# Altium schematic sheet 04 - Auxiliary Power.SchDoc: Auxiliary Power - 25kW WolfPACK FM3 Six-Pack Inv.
size 431 x 279 mm; Date: 01/2024; DocumentNumber: CRD25DA12N-FMC; Revision: 1.2; SheetNumber: 4; SheetTotal: 8; SheetSize: B
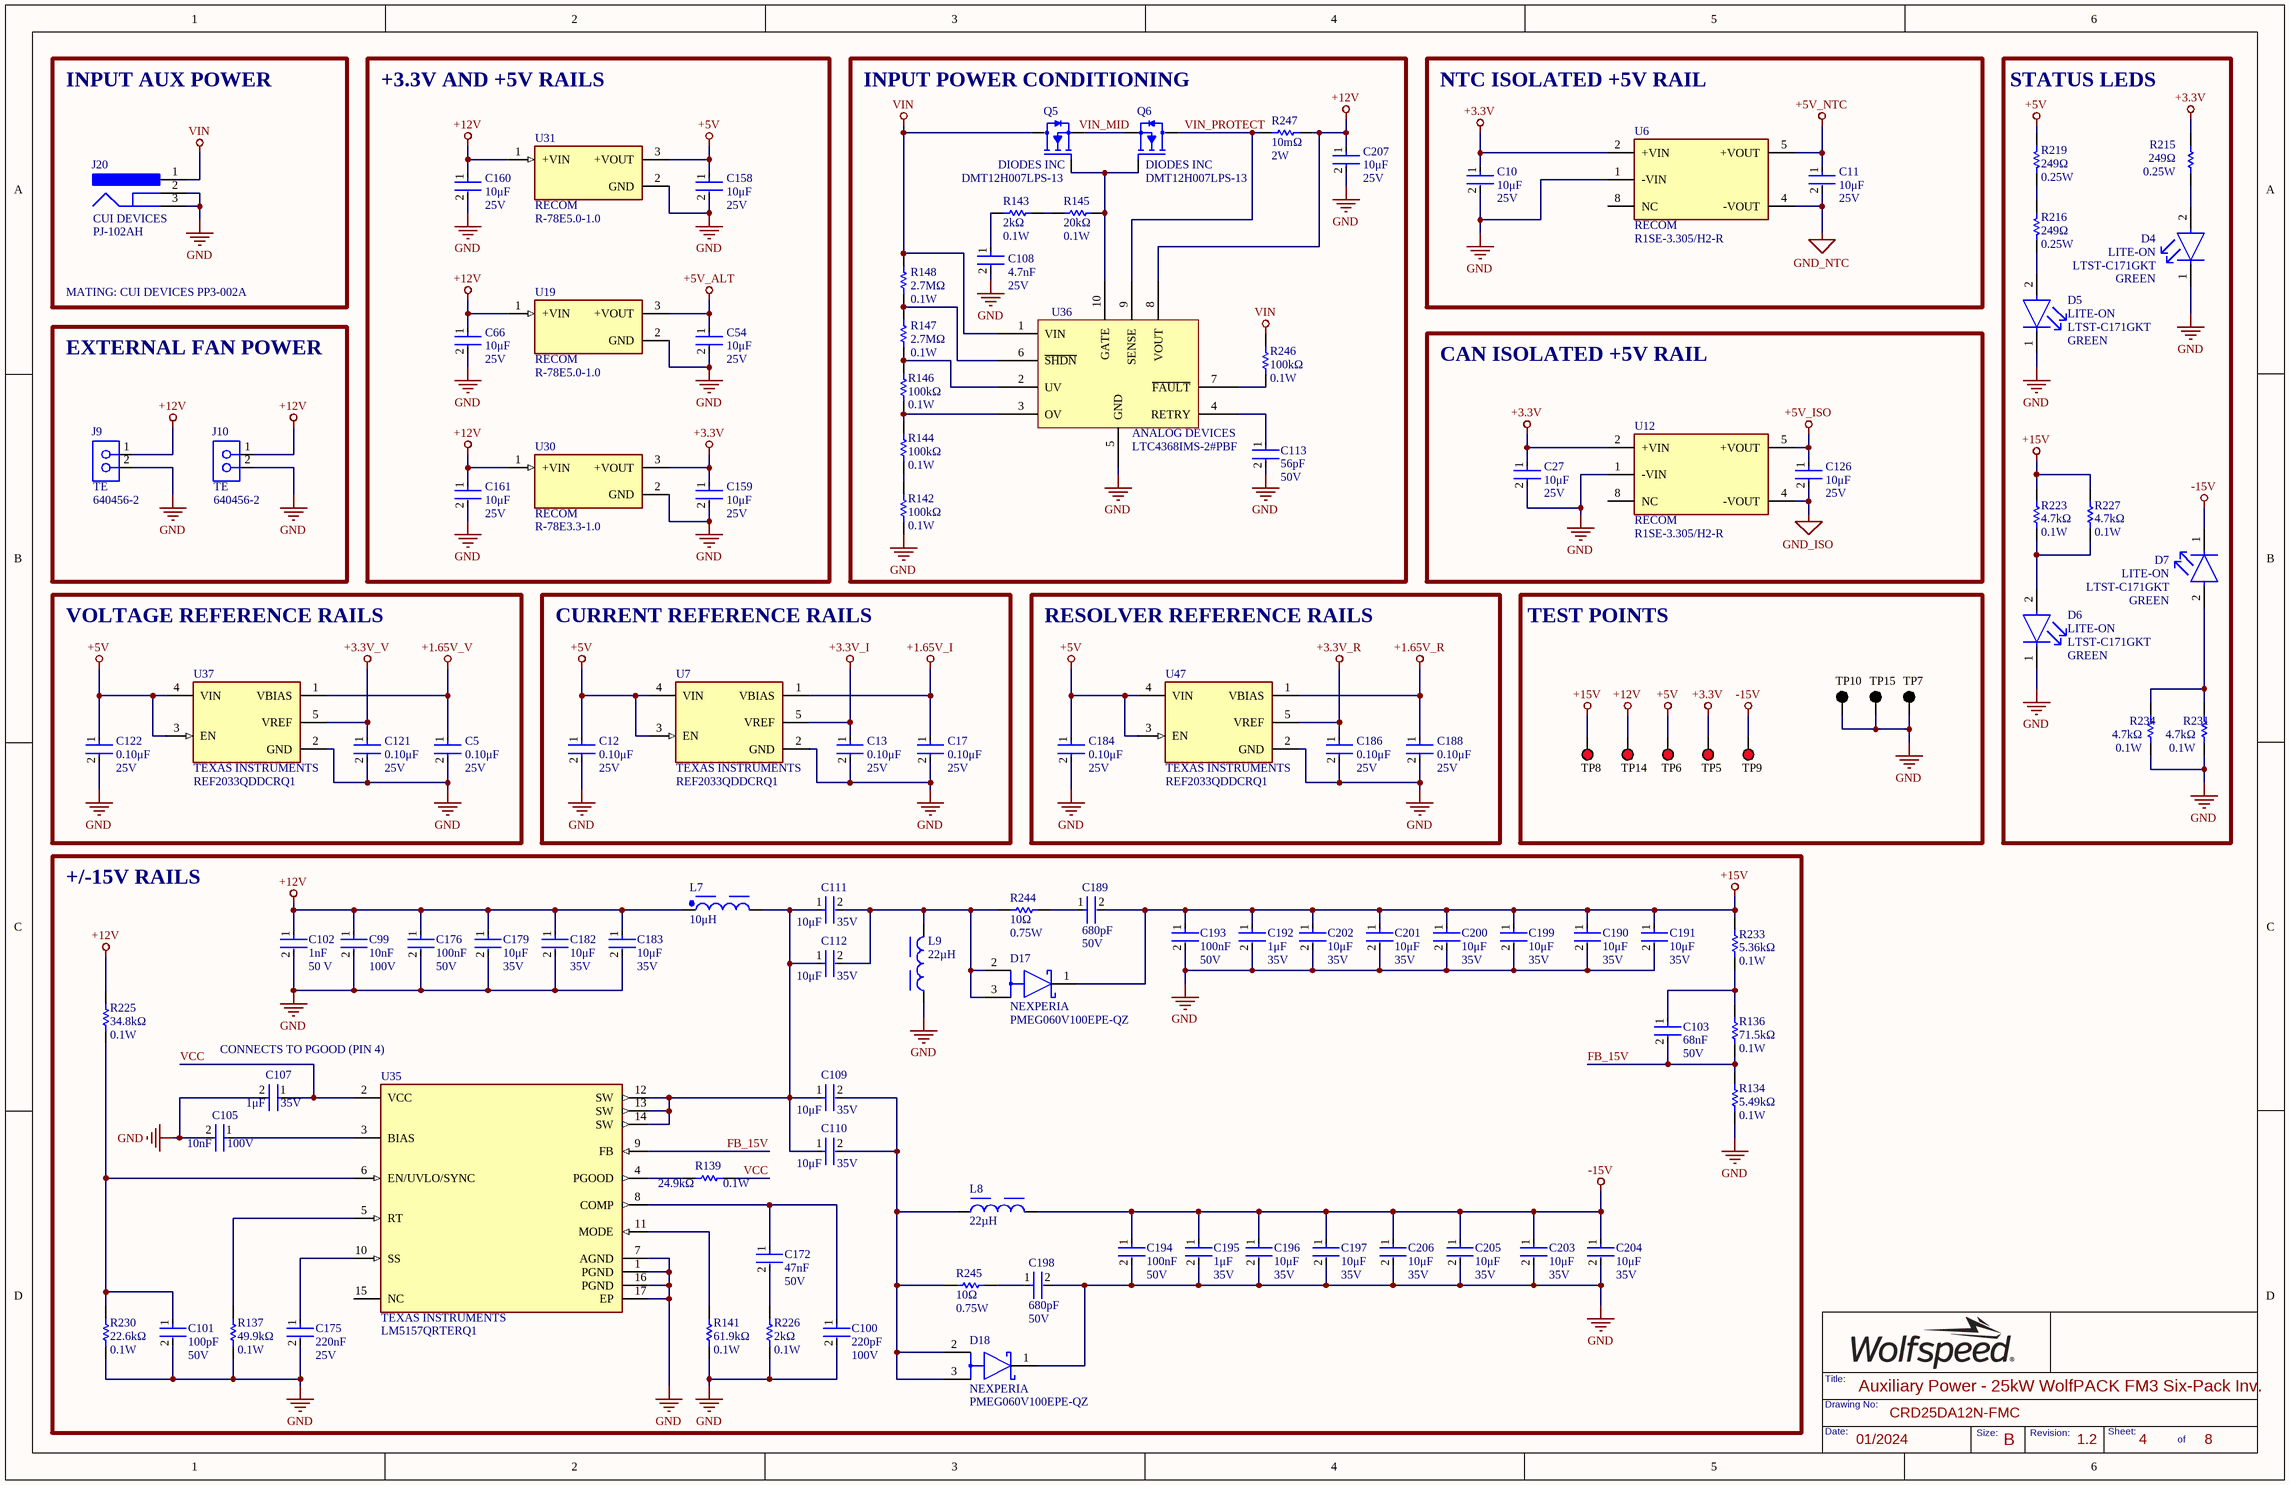
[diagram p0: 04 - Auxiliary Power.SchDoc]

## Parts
C5  Voltage Rating: 25V  Capacitance: 0.10μF  [FP-C0603C-CF-IPC_B]  (hidden comment: C0603C104K3RACTU)
C10  Voltage Rating: 25V  Capacitance: 10μF  [FP-CL31-IPC_B]  (hidden comment: CL31B106KAHSFNE)
C11  Voltage Rating: 25V  Capacitance: 10μF  [FP-CL31-IPC_B]  (hidden comment: CL31B106KAHSFNE)
C12  Voltage Rating: 25V  Capacitance: 0.10μF  [FP-C0603C-CF-IPC_B]  (hidden comment: C0603C104K3RACTU)
C13  Voltage Rating: 25V  Capacitance: 0.10μF  [FP-C0603C-CF-IPC_B]  (hidden comment: C0603C104K3RACTU)
C17  Voltage Rating: 25V  Capacitance: 0.10μF  [FP-C0603C-CF-IPC_B]  (hidden comment: C0603C104K3RACTU)
C27  Voltage Rating: 25V  Capacitance: 10μF  [FP-CL31-IPC_B]  (hidden comment: CL31B106KAHSFNE)
C54  Voltage Rating: 25V  Capacitance: 10μF  [FP-CL31-IPC_B]  (hidden comment: CL31B106KAHSFNE)
C66  Voltage Rating: 25V  Capacitance: 10μF  [FP-CL31-IPC_B]  (hidden comment: CL31B106KAHSFNE)
C99  value 10nF  Voltage Rating: 100V  [FP-C0603C-CF-IPC_B]  (hidden comment: GCM188R72A103KA37D)
C100  value 220pF  Voltage Rating: 100V  [FP-C0603C-CF-IPC_B]  (hidden comment: GCM1885C2A221JA16D)
C101  Capacitance: 100pF  Voltage: 50V  [FP-C0603C-CF-IPC_B]  (hidden comment: CL10C101JB8NNNC)
C102  Capacitance: 1nF  Voltage Rating: 50 V  [FP-C0603C-CF-IPC_B]  (hidden comment: C0603C102K5RACAUTO)
C103  value 68nF  Voltage Rating (DC): 50V  [FP-C0603C-CF-IPC_B]  (hidden comment: CGA3E2X7R1H683K080AA)
C105  value 10nF  Voltage Rating: 100V  [FP-C0603C-CF-IPC_B]  (hidden comment: GCM188R72A103KA37D)
C107  value 1μF  Voltage Rating: 35V  [FP-C0603C-CF-IPC_B]  (hidden comment: CGA3E1X7R1V105K080AC)
C108  Voltage Rating: 25V  Capacitance: 4.7nF  [FP-C0603C-CF-IPC_B]  (hidden comment: C0603C472K3RAC7867)
C109  value 10μF  Voltage Rating: 35V  [FP-C0603C-CF-IPC_B]  (hidden comment: GRM188R6YA106MA73D)
C110  value 10μF  Voltage Rating: 35V  [FP-C0603C-CF-IPC_B]  (hidden comment: GRM188R6YA106MA73D)
C111  value 10μF  Voltage Rating: 35V  [FP-C0603C-CF-IPC_B]  (hidden comment: GRM188R6YA106MA73D)
C112  value 10μF  Voltage Rating: 35V  [FP-C0603C-CF-IPC_B]  (hidden comment: GRM188R6YA106MA73D)
C113  Capacitance: 56pF  Voltage Rating: 50V  [FP-C0603C-CF-IPC_B]  (hidden comment: CL10C560JB8NNNC)
C121  Voltage Rating: 25V  Capacitance: 0.10μF  [FP-C0603C-CF-IPC_B]  (hidden comment: C0603C104K3RACTU)
C122  Voltage Rating: 25V  Capacitance: 0.10μF  [FP-C0603C-CF-IPC_B]  (hidden comment: C0603C104K3RACTU)
C126  Voltage Rating: 25V  Capacitance: 10μF  [FP-CL31-IPC_B]  (hidden comment: CL31B106KAHSFNE)
C158  Voltage Rating: 25V  Capacitance: 10μF  [FP-CL31-IPC_B]  (hidden comment: CL31B106KAHSFNE)
C159  Voltage Rating: 25V  Capacitance: 10μF  [FP-CL31-IPC_B]  (hidden comment: CL31B106KAHSFNE)
C160  Voltage Rating: 25V  Capacitance: 10μF  [FP-CL31-IPC_B]  (hidden comment: CL31B106KAHSFNE)
C161  Voltage Rating: 25V  Capacitance: 10μF  [FP-CL31-IPC_B]  (hidden comment: CL31B106KAHSFNE)
C172  value 47nF  Voltage Rating: 50V  [FP-C0603C-CF-IPC_B]  (hidden comment: CGA3E2X7R1H473K080AA)
C175  Capacitance: 220nF  Voltage: 25V  [FP-C0603C-CF-IPC_B]  (hidden comment: GCM188R71E224KA55D)
C176  value 100nF  Voltage: 50V  [FP-C0603C-CF-IPC_B]  (hidden comment: CGA3E2X7R1H104K080AA)
C179  value 10μF  Voltage Rating: 35V  [FP-C0603C-CF-IPC_B]  (hidden comment: GRM188R6YA106MA73D)
C182  value 10μF  Voltage Rating: 35V  [FP-C0603C-CF-IPC_B]  (hidden comment: GRM188R6YA106MA73D)
C183  value 10μF  Voltage Rating: 35V  [FP-C0603C-CF-IPC_B]  (hidden comment: GRM188R6YA106MA73D)
C184  Voltage Rating: 25V  Capacitance: 0.10μF  [FP-C0603C-CF-IPC_B]  (hidden comment: C0603C104K3RACTU)
C186  Voltage Rating: 25V  Capacitance: 0.10μF  [FP-C0603C-CF-IPC_B]  (hidden comment: C0603C104K3RACTU)
C188  Voltage Rating: 25V  Capacitance: 0.10μF  [FP-C0603C-CF-IPC_B]  (hidden comment: C0603C104K3RACTU)
C189  value 680pF  Voltage: 50V  [FP-C0603C-CF-IPC_B]  (hidden comment: C0603C681J5GACTU)
C190  value 10μF  Voltage Rating: 35V  [FP-C0603C-CF-IPC_B]  (hidden comment: GRM188R6YA106MA73D)
C191  value 10μF  Voltage Rating: 35V  [FP-C0603C-CF-IPC_B]  (hidden comment: GRM188R6YA106MA73D)
C192  value 1μF  Voltage Rating: 35V  [FP-C0603C-CF-IPC_B]  (hidden comment: CGA3E1X7R1V105K080AC)
C193  value 100nF  Voltage: 50V  [FP-C0603C-CF-IPC_B]  (hidden comment: CGA3E2X7R1H104K080AA)
C194  value 100nF  Voltage: 50V  [FP-C0603C-CF-IPC_B]  (hidden comment: CGA3E2X7R1H104K080AA)
C195  value 1μF  Voltage Rating: 35V  [FP-C0603C-CF-IPC_B]  (hidden comment: CGA3E1X7R1V105K080AC)
C196  value 10μF  Voltage Rating: 35V  [FP-C0603C-CF-IPC_B]  (hidden comment: GRM188R6YA106MA73D)
C197  value 10μF  Voltage Rating: 35V  [FP-C0603C-CF-IPC_B]  (hidden comment: GRM188R6YA106MA73D)
C198  value 680pF  Voltage: 50V  [FP-C0603C-CF-IPC_B]  (hidden comment: C0603C681J5GACTU)
C199  value 10μF  Voltage Rating: 35V  [FP-C0603C-CF-IPC_B]  (hidden comment: GRM188R6YA106MA73D)
C200  value 10μF  Voltage Rating: 35V  [FP-C0603C-CF-IPC_B]  (hidden comment: GRM188R6YA106MA73D)
C201  value 10μF  Voltage Rating: 35V  [FP-C0603C-CF-IPC_B]  (hidden comment: GRM188R6YA106MA73D)
C202  value 10μF  Voltage Rating: 35V  [FP-C0603C-CF-IPC_B]  (hidden comment: GRM188R6YA106MA73D)
C203  value 10μF  Voltage Rating: 35V  [FP-C0603C-CF-IPC_B]  (hidden comment: GRM188R6YA106MA73D)
C204  value 10μF  Voltage Rating: 35V  [FP-C0603C-CF-IPC_B]  (hidden comment: GRM188R6YA106MA73D)
C205  value 10μF  Voltage Rating: 35V  [FP-C0603C-CF-IPC_B]  (hidden comment: GRM188R6YA106MA73D)
C206  value 10μF  Voltage Rating: 35V  [FP-C0603C-CF-IPC_B]  (hidden comment: GRM188R6YA106MA73D)
C207  Voltage Rating: 25V  Capacitance: 10μF  [FP-CL31-IPC_B]  (hidden comment: CL31B106KAHSFNE)
D4  value GREEN  Manufacturer: LITE-ON  [FP-LTST-C171GKT-MFG]  (hidden comment: LTST-C171GKT)
D5  value GREEN  Manufacturer: LITE-ON  [FP-LTST-C171GKT-MFG]  (hidden comment: LTST-C171GKT)
D6  value GREEN  Manufacturer: LITE-ON  [FP-LTST-C171GKT-MFG]  (hidden comment: LTST-C171GKT)
D7  value GREEN  Manufacturer: LITE-ON  [FP-LTST-C171GKT-MFG]  (hidden comment: LTST-C171GKT)
D17  Manufacturer: NEXPERIA  [FP-PSMC_TO-277A-MFG]  (hidden comment: PMEG060V100EPE-QZ)
D18  Manufacturer: NEXPERIA  [FP-PSMC_TO-277A-MFG]  (hidden comment: PMEG060V100EPE-QZ)
J9  640456-2  Manufacturer Print: TE  [TECO-640456-2_V]
J10  640456-2  Manufacturer Print: TE  [TECO-640456-2_V]
J20  PJ-102AH  Manufacturer Print: CUI DEVICES  [CUI-PJ-102B_V]
L7  value 10μH  [WE-XHMI_8080_L8.8W8.3H7.8]  (hidden comment: 74439358100)
L8  value 22µH  [74437368220]  (hidden comment: 74437368220)
L9  value 22µH  [74437368220]  (hidden comment: 74437368220)
Q5  DMT12H007LPS-13  Manufacturer: DIODES INC  [FP-PowerDI5060-8-MFG]
Q6  DMT12H007LPS-13  Manufacturer: DIODES INC  [FP-PowerDI5060-8-MFG]
R134  value 5.49kΩ  Power Rating: 0.1W  [FP-MCR03-IPC_B]  (hidden comment: RC0603FR-075K49L)
R136  value 71.5kΩ  Max Power Dissipation: 0.1W  [FP-MCR03-IPC_B]  (hidden comment: RT0603DRE0771K5L)
R137  value 49.9kΩ  Power Rating: 0.1W  [FP-MCR03-IPC_B]  (hidden comment: RT0603FRE0749K9L)
R139  value 24.9kΩ  Power Rating: 0.1W  [FP-MCR03-IPC_B]  (hidden comment: RC0603FR-0724K9L)
R141  value 61.9kΩ  Power Rating: 0.1W  [FP-MCR03-IPC_B]  (hidden comment: RC0603FR-0761K9L)
R142  Resistance: 100kΩ  Power Rating: 0.1W  [FP-MCR03-IPC_B]  (hidden comment: RC0603FR-07100KL)
R143  Resistance: 2kΩ  Power Rating: 0.1W  [FP-MCR03-IPC_B]  (hidden comment: RT0603DRE072KL)
R144  Resistance: 100kΩ  Power Rating: 0.1W  [FP-MCR03-IPC_B]  (hidden comment: RC0603FR-07100KL)
R145  Resistance: 20kΩ  Power Rating: 0.1W  [FP-MCR03-IPC_B]  (hidden comment: CRCW060320K0FKTA)
R146  Resistance: 100kΩ  Power Rating: 0.1W  [FP-MCR03-IPC_B]  (hidden comment: RC0603FR-07100KL)
R147  Power Rating: 0.1W  Resistance: 2.7MΩ  [FP-MCR03-IPC_B]  (hidden comment: RC0603JR-072M7L)
R148  Power Rating: 0.1W  Resistance: 2.7MΩ  [FP-MCR03-IPC_B]  (hidden comment: RC0603JR-072M7L)
R215  Resistance: 249Ω  Power Rating: 0.25W  [FP-MCR18-IPC_A]  (hidden comment: RC1206FR-07249RL)
R216  Resistance: 249Ω  Power Rating: 0.25W  [FP-MCR18-IPC_A]  (hidden comment: RC1206FR-07249RL)
R219  Resistance: 249Ω  Power Rating: 0.25W  [FP-MCR18-IPC_A]  (hidden comment: RC1206FR-07249RL)
R223  Resistance: 4.7kΩ  Power Rating: 0.1W  [FP-MCR03-IPC_B]  (hidden comment: CRCW06034K70FKTA)
R225  value 34.8kΩ  Power Rating: 0.1W  [FP-MCR03-IPC_B]  (hidden comment: RT0603DRE0734K8L)
R226  Resistance: 2kΩ  Power Rating: 0.1W  [FP-MCR03-IPC_B]  (hidden comment: RT0603DRE072KL)
R227  Resistance: 4.7kΩ  Power Rating: 0.1W  [FP-MCR03-IPC_B]  (hidden comment: CRCW06034K70FKTA)
R230  value 22.6kΩ  Max Power Dissipation: 0.1W  [FP-MCR03-IPC_B]  (hidden comment: RT0603DRE0722K6L)
R231  Resistance: 4.7kΩ  Power Rating: 0.1W  [FP-MCR03-IPC_B]  (hidden comment: CRCW06034K70FKTA)
R233  value 5.36kΩ  Power Rating: 0.1W  [FP-MCR03-IPC_B]  (hidden comment: RT0603BRD075K36L)
R234  Resistance: 4.7kΩ  Power Rating: 0.1W  [FP-MCR03-IPC_B]  (hidden comment: CRCW06034K70FKTA)
R244  value 10Ω  Power Rating: 0.75W  [RESC3125X70X40NL20T20]  (hidden comment: CRCW121010R0FKEAHP)
R245  value 10Ω  Power Rating: 0.75W  [RESC3125X70X40NL20T20]  (hidden comment: CRCW121010R0FKEAHP)
R246  Resistance: 100kΩ  Power Rating: 0.1W  [FP-MCR03-IPC_B]  (hidden comment: RC0603FR-07100KL)
R247  Resistance: 10mΩ  Max Power Dissipation: 2W  [FP-RL2512-IPC_A]  (hidden comment: PE2512FKE7W0R01L)
TP5  5010  [KSTN-5010_V]  (value not drawn)
TP6  5010  [KSTN-5010_V]  (value not drawn)
TP7  5011  [KSTN-5011_V]  (value not drawn)
TP8  5010  [KSTN-5010_V]  (value not drawn)
TP9  5010  [KSTN-5010_V]  (value not drawn)
TP10  5011  [KSTN-5011_V]  (value not drawn)
TP14  5010  [KSTN-5010_V]  (value not drawn)
TP15  5011  [KSTN-5011_V]  (value not drawn)
U6  Manufacturer: RECOM  [FP-R1SE-0505-R-MFG]  (hidden comment: R1SE-3.305/H2-R)
U7  Manufacturer: TEXAS INSTRUMENTS  [FP-DDC0005A-MFG]  (hidden comment: REF2033QDDCRQ1)
U12  Manufacturer: RECOM  [FP-R1SE-0505-R-MFG]  (hidden comment: R1SE-3.305/H2-R)
U19  R-78E5.0-1.0  Manufacturer Print: RECOM  [CONV_R-78E5.0-1.0]
U30  R-78E3.3-1.0  Manufacturer Print: RECOM  [CONV_R-78E3.3-1.0]
U31  R-78E5.0-1.0  Manufacturer Print: RECOM  [CONV_R-78E5.0-1.0]
U35  Manufacturer: TEXAS INSTRUMENTS  [FP-RTE0016K-IPC_A]  (hidden comment: LM5157QRTERQ1)
U36  LTC4368IMS-2#PBF  Manufacturer Print: ANALOG DEVICES  [SOP50P490X110-10N]
U37  Manufacturer: TEXAS INSTRUMENTS  [FP-DDC0005A-MFG]  (hidden comment: REF2033QDDCRQ1)
U47  Manufacturer: TEXAS INSTRUMENTS  [FP-DDC0005A-MFG]  (hidden comment: REF2033QDDCRQ1)

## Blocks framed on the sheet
INPUT AUX POWER: J20
+3.3V AND +5V RAILS: C54 C66 C158-C161 U19 U30 U31
INPUT POWER CONDITIONING: C108 C113 C207 Q5 Q6 R142-R148 R246 R247 U36
NTC ISOLATED +5V RAIL: C10 C11 U6
STATUS LEDS: D4-D7 R215 R216 R219 R223 R227 R231 R234
EXTERNAL FAN POWER: J9 J10
CAN ISOLATED +5V RAIL: C27 C126 U12
VOLTAGE REFERENCE RAILS: C5 C121 C122 U37
CURRENT REFERENCE RAILS: C12 C13 C17 U7
RESOLVER REFERENCE RAILS: C184 C186 C188 U47
TEST POINTS: TP5-TP10 TP14 TP15
+/-15V RAILS: C99-C103 C105 C107 C109-C112 C172 C175 C176 C179 C182 C183 C189-C206 D17 D18 L7-L9 R134 R136 R137 R139 R141 R225 R226 R230 R233 R244 R245 U35

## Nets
+1.65V_I: C17.1 U7.1(VBIAS)
+1.65V_R: C188.1 U47.1(VBIAS)
+1.65V_V: C5.1 U37.1(VBIAS)
+3.3V: C10.1 C27.1 C159.1 R215.1 TP5.1 U6.2(+VIN) U12.2(+VIN) U30.3(+VOUT)
+3.3V_I: C13.1 U7.5(VREF)
+3.3V_R: C186.1 U47.5(VREF)
+3.3V_V: C121.1 U37.5(VREF)
+5V: C12.1 C122.1 C158.1 C184.1 R219.1 TP6.1 U7.3(EN) U7.4(VIN) U31.3(+VOUT) U37.3(EN) U37.4(VIN) U47.3(EN) U47.4(VIN)
+5V_ALT: C54.1 U19.3(+VOUT)
+5V_ISO: C126.1 U12.5(+VOUT)
+5V_NTC: C11.1 U6.5(+VOUT)
+12V: C66.1 C99.1 C102.1 C160.1 C161.1 C176.1 C179.1 C182.1 C183.1 C207.1 J9.1 J10.1 L7.1 R225.2 R247.2 TP14.1 U19.1(+VIN) U30.1(+VIN) U31.1(+VIN) U36.8(VOUT)
+15V: C189.2 C190.1 C191.1 C192.1 C193.1 C199.1 C200.1 C201.1 C202.1 D17.1(K) R223.2 R227.2 R233.2 TP8.1
-15V: C194.1 C195.1 C196.1 C197.1 C203.1 C204.1 C205.1 C206.1 D7.1(C) L8.2 TP9.1
GND: C5.2 C10.2 C12.2 C13.2 C17.2 C27.2 C54.2 C66.2 C99.2 C100.2 C101.2 C102.2 C105.2 C107.2 C108.2 C113.2 C121.2 C122.2 C158.2 C159.2 C160.2 C161.2 C175.2 C176.2 C179.2 C182.2 C183.2 C184.2 C186.2 C188.2 C190.2 C191.2 C192.2 C193.2 C194.2 C195.2 C196.2 C197.2 C198.2 C199.2 C200.2 C201.2 C202.2 C203.2 C204.2 C205.2 C206.2 C207.2 D4.1(C) D5.1(C) D6.1(C) D18.1(K) J9.2 J10.2 J20.2 J20.3 L9.1 R134.1 R137.1 R141.1 R142.1 R226.1 R230.1 R231.1 R234.1 TP7.1 TP10.1 TP15.1 U6.1(-VIN) U7.2(GND) U12.1(-VIN) U19.2(GND) U30.2(GND) U31.2(GND) U35.1(PGND) U35.7(AGND) U35.16(PGND) U35.17(EP) U36.5(GND) U37.2(GND) U47.2(GND)
GND_ISO: C126.2 U12.4(-VOUT)
GND_NTC: C11.2 U6.4(-VOUT)
VIN: J20.1 Q5.5(D) R148.2 R246.2 U36.1(VIN)
FB_15V: C103.2 R134.2 R136.1 U35.9(FB)
VCC: C107.1 R139.2 U35.2(VCC)
VIN_MID: Q5.1,2,3(S) Q6.1,2,3(S)
VIN_PROTECT: Q6.5(D) R247.1 U36.9(SENSE)
NetC100_1: C100.1 C172.1 U35.8(COMP)
NetC101_1: C101.1 R225.1 R230.2 U35.6(EN/UVLO/SYNC)
NetC103_1: C103.1 R136.2 R233.1
NetC105_1: C105.1 U35.3(BIAS)
NetC108_1: C108.1 R143.1
NetC109_1: C109.1 C110.1 C111.1 C112.1 L7.2 U35.12(SW) U35.13(SW) U35.14(SW)
NetC109_2: C109.2 C110.2 D18.2(A) D18.3(A) L8.1 R245.1
NetC111_2: C111.2 C112.2 D17.2(A) D17.3(A) L9.2 R244.1
NetC113_1: C113.1 U36.4(RETRY)
NetC172_2: C172.2 R226.2
NetC175_1: C175.1 U35.10(SS)
NetC189_1: C189.1 R244.2
NetC198_1: C198.1 R245.2
NetD4_2: D4.2(A) R215.2
NetD5_2: D5.2(A) R216.2
NetD6_2: D6.2(A) R223.1 R227.1
NetD7_2: D7.2(A) R231.2 R234.2
NetQ5_4: Q5.4(G) Q6.4(G) R145.2 U36.10(GATE)
NetR137_2: R137.2 U35.5(RT)
NetR139_1: R139.1 U35.4(PGOOD)
NetR141_2: R141.2 U35.11(MODE)
NetR142_2: R142.2 R144.1
NetR143_2: R143.2 R145.1
NetR144_2: R144.2 R146.1 U36.3(OV)
NetR146_2: R146.2 R147.1 U36.2(UV)
NetR147_2: R147.2 R148.1 U36.6(~{SHDN})
NetR216_1: R216.1 R219.2
NetR246_1: R246.1 U36.7(~{FAULT})

Not connected (* = marked no-connect by the designer): U6 8(NC); U12 8(NC); U35 15(NC)

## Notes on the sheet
- MATING: CUI DEVICES PP3-002A
- CONNECTS TO PGOOD (PIN 4)

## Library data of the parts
C5 C12 C13 C17 C121 C122 C184 C186 C188 = CMP-2006-03057-2: CAP CER 0.1UF 25V X7R 0603; Manufacturer: KEMET; Value: 0.10μF; Material: Ceramic; Tolerance: 0.1; Temperature Coefficient: 30ppm/°C; Automotive Grade: Grade 1
C10 C11 C27 C54 C66 C126 C158-C161 C207 = CMP-13271-001434-1: CAP CER 10UF 25V X7R 1206; Manufacturer: SAMSUNG; Tolerance: 10%; Value: 10μF
C99 C105 = GCM188R72A103KA37D: CAP CER 10000PF 100V X7R 0603; Manufacturer: MURATA; Material: 4241ConductorMaterial; Tolerance: 10%
C100 = GCM1885C2A221JA16D: CAP CER 220PF 100V C0G/NP0 0603; Manufacturer: MURATA; Material: 4241ConductorMaterial; Tolerance: 5%; Dielectric: C0G; Dissipation Factor: 0.01%; Temperature Coefficient: 30ppm/°C
C101 = CL10C101JB8NNNC: CAP CER 100PF 50V C0G/NP0 0603; Manufacturer: SAMSUNG; Material: Ceramic; Tolerance: 5%; Dielectric: C0G; Temperature Coefficient: 300ppm/°C
C102 = CMP-2006-03716-2: CAP CER 1000PF 50V X7R 0603; Manufacturer: KEMET; Material: Ceramic; Automotive Grade: Grade 1; Value: 1nF; Tolerance: 0.1; Temperature Coefficient: 30ppm/°C
C103 = CGA3E2X7R1H683K080AA: CAP CER 0.068UF 50V X7R 0603; Manufacturer: TDK; Tolerance: 10%
C107 C192 C195 = CGA3E1X7R1V105K080AC: CAP CER 1UF 35V X7R 0603; Manufacturer: TDK; Material: 4241ConductorMaterial; Tolerance: 10%
C108 = C0603C472K3RAC7867: CAP CER 4700PF 25V 10% X7R 0603; Manufacturer: KEMET; Manufacturer Part Number: C0603C472K3RACTU; Dielectric Material: Ceramic; Value: 4.7nF
C109-C112 C179 C182 C183 C190 C191 C196 C197 C199-C206 = GRM188R6YA106MA73D: CAP CER 10UF 35V X5R 0603; Manufacturer: MURATA; Material: 4241ConductorMaterial; Tolerance: 20%
C113 = CL10C560JB8NNNC: CAP CER 56PF 50V C0G/NP0 0603; Manufacturer: SAMSUNG; Material: Ceramic; Tolerance: 5%; Dielectric: C0G; Temperature Coefficient: 30ppm/°C
C172 = CGA3E2X7R1H473K080AA: CAP CER 0.047UF 50V X7R 0603; Manufacturer: TDK; Material: 4241ConductorMaterial; Tolerance: 10%
C175 = GCM188R71E224KA55D: CAP CER 0.22UF 25V X7R 0603; Manufacturer: MURATA; Material: 4241ConductorMaterial; Tolerance: 10%; Value: 220nF
C176 C193 C194 = CGA3E2X7R1H104K080AA: CAP CER 0.1UF 50V X7R 0603; Manufacturer: TDK; Material: 4241ConductorMaterial; Tolerance: 10%
C189 C198 = C0603C681J5GACTU: CAP CER 680PF 50V C0G/NP0 0603; Manufacturer: KEMET; Dielectric Material: Ceramic; Material: 4241ConductorMaterial; Tolerance: 5%; Dielectric: C0G; Temperature Coefficient: 30ppm/°C; Dissipation Factor: 0.1%
D4-D7 = CMP-22017-000007-1: LED GREEN CLEAR CHIP SMD; Luminous Intensity: 12mcd; Lens Color: Colorless; Dominant Wavelength: 569nm; Number of LEDs: 1; Power Dissipation: 100mW; Viewing Angle: 130°; Reverse Voltage: 5V; Test Current: 10mA; Forward Voltage: 2.1V; Wavelength: 585nm; Lens Style: Diffused; Forward Current: 30mA
D17 D18 = PMEG060V100EPE-QZ: DIODE SCHOTTKY 60V 10A CFP15B
J9 J10 = CMP-2000-05417-1: CONN HEADER VERT 2POS 2.54MM; Standards: RoHSCompliant,ELVCompliant,UL94V-0; Material, Housing: Polyester; Agency Approvals: CSA,UL; Brand/Series: MTA-100Series; Contact Centerline Spacing: 0.100 / in.; Material, Contact: CopperAlloy; Current, Rating: 5 / A; Color, Housing: White; Contact Termination Area Plating: Tin; Special Features: Pinstrip; Number of Positions: 2; Pin Spacing: 0.1 / "; Temperature, Operating: -55to+105 / degC; Angle: Straight; Mount Angle: Vertical; Connector Type: MTA-100; Primary Type: InterconnectSystem; Voltage, Rating: 250 / V; Mounting Hole Size: 0.04 / "
J20 = PJ-102AH: CONN PWR JACK 2X5.5MM SOLDER; Gender: Male; Shielding: Unshielded; Current Rating: 5A; Voltage Rating: 24V; Insulation Resistance: 50MR; Number of Conductors: 2
L7 = 74439358100: FIXED IND 10UH 5.8A 20 MOHM SMD; Manufacturer: WURTH ELECTRONIK
L8 L9 = 74437368220: FIXED IND 22UH 3.5A 74 MOHM SMD; NexarPartId: 57062130; Manufacturer: WURTH ELECTRONIK; Tolerance: 20%; Series Resistance: 74mΩ; Saturation Current: 5A; DC Resistance (DCR): 64mΩ; Self Resonant Frequency: 7MHz; Test Frequency: 100kHz
Q5 Q6 = DMT12H007LPS-13: MOSFET N-CH 120V 90A PWRDI5060-8
R134 = RC0603FR-075K49L: RES 5.49K OHM 1% 1/10W 0603; Manufacturer: YAGEO; Temperature Coefficient: 100ppm/°C; Voltage Rating: 50V; Max Power Dissipation: 100mW
R136 = RT0603DRE0771K5L: RES SMD 71.5KOHM 0.5% 1/10W 0603; Manufacturer: YAGEO; Temperature Coefficient: 50ppm/°C; Voltage Rating (DC): 50V
R137 = RT0603FRE0749K9L: RES SMD 49.9K OHM 1% 1/10W 0603; Manufacturer: YAGEO; Temperature Coefficient: 50ppm/°C; Max Power Dissipation: 100mW; Voltage Rating: 75V; Voltage Rating (DC): 50V
R139 = RC0603FR-0724K9L: RES 24.9K OHM 1% 1/10W 0603; Manufacturer: YAGEO; Temperature Coefficient: 100ppm/°C; Max Power Dissipation: 100mW; Voltage Rating: 50V
R141 = RC0603FR-0761K9L: RES 61.9K OHM 1% 1/10W 0603; Manufacturer: YAGEO; Temperature Coefficient: 100ppm/°C; Max Power Dissipation: 100mW; Voltage Rating (DC): 50V; Working Voltage: 75V
R142 R144 R146 R246 = RC0603FR-07100KL: RES 100K OHM 1% 1/10W 0603; Manufacturer: YAGEO; Temperature Coefficient: 100ppm/°C; Voltage Rating: 50V; Working Voltage: 75V; Max Power Dissipation: 100mW; Value: 100kΩ
R143 R226 = RT0603DRE072KL: RES SMD 2K OHM 0.5% 1/10W 0603; Manufacturer: YAGEO; Temperature Coefficient: 50ppm/°C; Voltage Rating: 75V; Max Power Dissipation: 100mW; Voltage Rating (DC): 50V; Value: 2kΩ
R145 = CRCW060320K0FKTA: RES SMD 20K OHM 1% 1/10W 0603; Manufacturer: VISHAY DALE; Temperature Coefficient: 100ppm/°C; Voltage Rating: 75V; Max Power Dissipation: 100mW; Value: 20kΩ
R147 R148 = RC0603JR-072M7L: RES 2.7M OHM 5% 1/10W 0603; Manufacturer: YAGEO; Temperature Coefficient: 100ppm/°C; Voltage Rating: 75V; Max Power Dissipation: 100mW; Voltage Rating (DC): 50V; Value: 2.7MΩ
R215 R216 R219 = RC1206FR-07249RL: RES 249 OHM 1% 1/4W 1206; Manufacturer: YAGEO; Voltage Rating: 200V; Temperature Coefficient: 100ppm/°C; Max Power Dissipation: 250mW; Value: 249Ω
R223 R227 R231 R234 = CRCW06034K70FKTA: RES SMD 4.7K OHM 1% 1/10W 0603; Manufacturer: VISHAY DALE; Voltage Rating: 75V; Max Power Dissipation: 100mW; Temperature Coefficient: 100ppm/°C; Value: 4.7kΩ
R225 = RT0603DRE0734K8L: RES SMD 34.8KOHM 0.5% 1/10W 0603; Manufacturer: YAGEO; Temperature Coefficient: 50ppm/°C; Voltage Rating: 75V; Voltage Rating (DC): 50V; Max Power Dissipation: 100mW
R230 = RT0603DRE0722K6L: RES SMD 22.6KOHM 0.5% 1/10W 0603; Manufacturer: YAGEO; Temperature Coefficient: 50ppm/°C; Voltage Rating (DC): 50V
R233 = RT0603BRD075K36L: RES SMD 5.36KOHM 0.1% 1/10W 0603; Manufacturer: YAGEO; Temperature Coefficient: 25ppm/°C; Max Power Dissipation: 100mW; Voltage Rating: 75V; Voltage Rating (DC): 50V
R244 R245 = CRCW121010R0FKEAHP: RES SMD 10 OHM 1% 3/4W 1210; Manufacturer: VISHAY; Voltage Rating: 200V; Max Power Dissipation: 750mW; Temperature Coefficient: 100ppm/°C
R247 = PE2512FKE7W0R01L: RES 0.01 OHM 1% 2W 2512; Manufacturer: YAGEO; Temperature Coefficient: 50ppm/°C; Value: 10mΩ
TP5 TP6 TP8 TP9 TP14 = CMP-1672-00002-4: PC TEST POINT MULTIPURPOSE RED; Manufacturer: KEYSTONE
TP7 TP10 TP15 = CMP-1672-00003-4: PC TEST POINT MULTIPURPOSE BLACK; Manufacturer: KEYSTONE
U6 U12 = R1SE-3.305/H2-R: DC DC CONVERTER 5V 1W; Number of Outputs: 1; Min Input Voltage: 2.97V; Max Input Voltage: 3.63V; Max Output Current: 200mA; Isolation Voltage: 2kV; Efficiency: 75%
U7 U37 U47 = REF2033QDDCRQ1: AUTOMOTIVE LOW-DRIFT, LOW-POWER,
U19 U31 = R-78E5.0-1.0: DC DC CONVERTER 5V 5W; Number of Outputs: 1; Min Input Voltage: 8V; Max Input Voltage: 28V; Max Output Current: 1A; Efficiency: 91%
U30 = R-78E3.3-1.0: DC DC CONVERTER 3.3V 3W; Number of Outputs: 1; Min Input Voltage: 8V; Max Input Voltage: 28V; Max Output Current: 1A; Efficiency: 91%; Max Output Power: 3.3W; Min Input Voltage (DC): 7V
U35 = LM5157QRTERQ1: IC REG MULT CONFG ADJ 6.5A 16QFN
U36 = LTC4368IMS-2#PBF: IC SURGE SUPPRESSION ADJ 10MSOP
